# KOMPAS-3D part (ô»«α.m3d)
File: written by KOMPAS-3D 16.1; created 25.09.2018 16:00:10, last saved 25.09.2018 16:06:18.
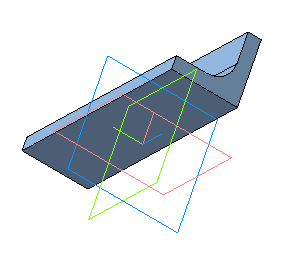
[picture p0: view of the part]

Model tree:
1. Эскиз:1
2. Вырезать элемент выдавливания:1
     Расстояние 2 = 10
3. Эскиз:2
4. Вырезать элемент выдавливания:2  (labels: SYSTEM_PROPERTY_ADDITIONAL_FOR:5.000000)
     Расстояние 2 = 10; Ориентация = 2; Расстояние = -50

Referenced files in C:\Program Files\ASCON\KOMPAS-3D V16\Libs\PartLib\DATA\vault\Methods\Kompas\3D\: PLib_Angle_GOST_8509_1501.m3d
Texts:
  Уголок 100x63x6 ГОСТ 8510-86
  (+) Уголок 100x63x6 ГОСТ 8510-86
  ГОСТ 8510-86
